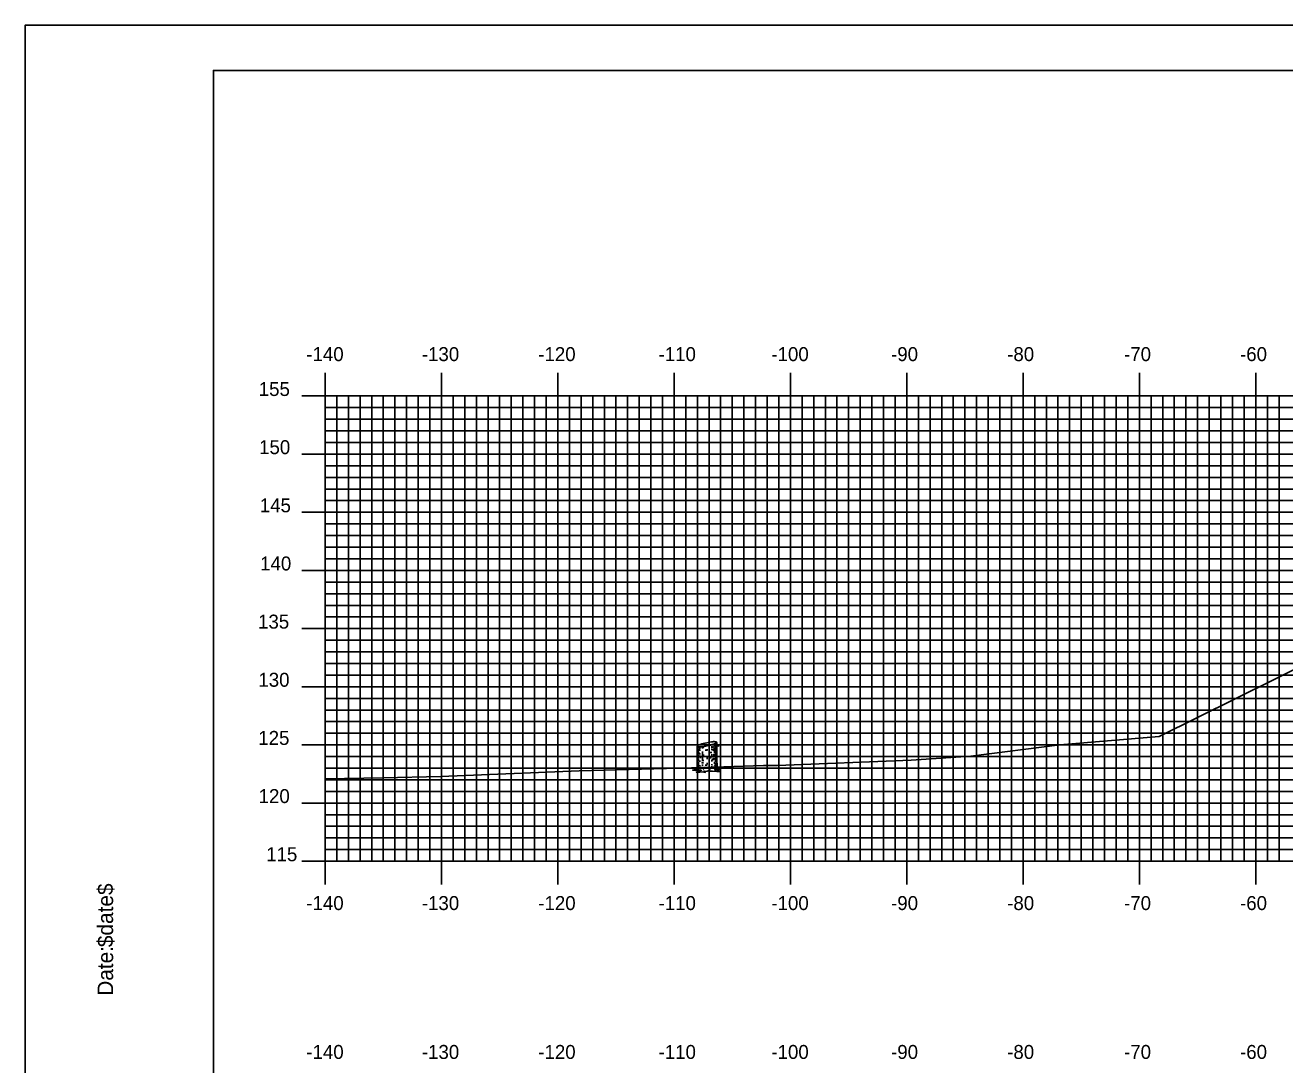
# Model space of a CAD drawing. Extents: x 851360 to 851703, y 364661 to 364881.
# Drawn here: x 851359.9 to 851468.2, y 364791.9 to 364881.3 of the extents above; entities that cross this region are included whole.
import ezdxf

# ---------------------------------------------------------------- set-up
doc = ezdxf.new("R2010")
doc.units = 0
for name, color, linetype in [('BORDER', 7, 'Continuous'), ('H_V ANNOTATION', 7, 'Continuous'), ('M_Trees_Conifer_Pay', 7, 'Continuous'), ('MAJOR', 7, 'Continuous'), ('MINOR', 7, 'Continuous'), ('PLOT BOUNDARY', 7, 'Continuous'), ('S_Roadway_Centerline', 7, 'Continuous')]:
    doc.layers.add(name, color=color, linetype=linetype)

msp = doc.modelspace()

# ---------------------------------------------------------------- linework, layer by layer
at = {"layer": 'BORDER'}
msp.add_lwpolyline([(851376.13, 364667.37), (851696.13, 364667.37), (851696.13, 364877.37), (851376.13, 364877.37)], close=True, dxfattribs=at)
at = {"layer": 'M_Trees_Conifer_Pay'}
for p, q in [((851417.72, 364817.53), (851417.72, 364819.26)), ((851417.77, 364819.22), (851417.77, 364818.75)), ((851417.83, 364819.21), (851417.83, 364819.11)), ((851417.83, 364819.03), (851417.83, 364818.83)), ((851417.95, 364819.2), (851417.95, 364818.97)), ((851418.17, 364819.22), (851418.17, 364819.05)), ((851418.58, 364818.99), (851418.58, 364818.89)), ((851418.97, 364819.26), (851418.97, 364819.06)), ((851418.97, 364819), (851418.97, 364818.92)), ((851419.2, 364819.46), (851419.2, 364819.23)), ((851419.2, 364819.15), (851419.2, 364819.1)), ((851419.25, 364818.96), (851419.2, 364818.9)), ((851419.32, 364819.52), (851419.32, 364819.36)), ((851419.32, 364819.29), (851419.32, 364819.16)), ((851419.32, 364818.97), (851419.32, 364818.64)), ((851419.39, 364817.94), (851419.39, 364819.59)), ((851417.77, 364818.68), (851417.77, 364818.37)), ((851417.77, 364818.33), (851417.77, 364817.83)), ((851417.83, 364818.77), (851417.83, 364818.57)), ((851417.83, 364818.53), (851417.83, 364818.19)), ((851417.83, 364818.14), (851417.83, 364818)), ((851417.83, 364817.9), (851417.83, 364817.52)), ((851417.95, 364818.93), (851417.95, 364818.85)), ((851417.95, 364818.45), (851417.95, 364818.31)), ((851417.95, 364818.04), (851417.95, 364817.9)), ((851418.17, 364818.81), (851418.17, 364818.58)), ((851418.17, 364818.33), (851418.17, 364818.18)), ((851418.17, 364818.14), (851418.17, 364817.96)), ((851418.58, 364818.37), (851418.58, 364818.3)), ((851418.58, 364818.27), (851418.58, 364818.13)), ((851418.97, 364818.57), (851418.97, 364818.46)), ((851418.97, 364818.1), (851418.97, 364817.95)), ((851419.2, 364818.76), (851419.2, 364818.63)), ((851419.2, 364818.52), (851419.2, 364818.41)), ((851419.2, 364818.27), (851419.2, 364818.13)), ((851419.2, 364817.91), (851419.2, 364817.73)), ((851419.32, 364818.6), (851419.32, 364818.44)), ((851419.32, 364818.39), (851419.32, 364818.17)), ((851419.32, 364818.14), (851419.32, 364818.07)), ((851419.32, 364818.03), (851419.32, 364817.86)), ((851417.77, 364817.78), (851417.77, 364817.53)), ((851417.95, 364817.63), (851417.95, 364817.54)), ((851417.95, 364817.14), (851418.12, 364817.2)), ((851418.17, 364817.69), (851418.17, 364817.53)), ((851418.39, 364817.08), (851418.26, 364817.14)), ((851418.58, 364817.83), (851418.58, 364817.68)), ((851418.97, 364817.72), (851418.97, 364817.63))]:
    msp.add_line(p, q, dxfattribs=at)
for points in [[(851419.17, 364819.05), (851419.14, 364818.97), (851419.14, 364818.9), (851419.17, 364818.84)], [(851419.2, 364819.09), (851419.24, 364819.01), (851419.29, 364819.07), (851419.35, 364819.14), (851419.44, 364819.33), (851419.5, 364819.38), (851419.53, 364819.39)], [(851419.22, 364818.84), (851419.25, 364818.96), (851419.32, 364819.08), (851419.35, 364819.15), (851419.42, 364819.29)], [(851419.43, 364819.32), (851419.51, 364819.33), (851419.58, 364819.23)], [(851419.39, 364817.94), (851419.44, 364817.68), (851419.45, 364817.41), (851419.51, 364817.28), (851419.65, 364817.25), (851419.42, 364817.21), (851419.42, 364817.21), (851419.42, 364817.17), (851419.67, 364817.07), (851419.4, 364817.09), (851419.04, 364817.11), (851418.72, 364817.1), (851418.73, 364817.18), (851418.58, 364817.1), (851418.39, 364817.08), (851418.41, 364817.01), (851418.15, 364817.05), (851417.93, 364817.02), (851417.63, 364817.04), (851417.92, 364817.1), (851417.95, 364817.14), (851417.79, 364817.2), (851417.55, 364817.21), (851417.31, 364817.21), (851417.65, 364817.27), (851417.7, 364817.35), (851417.72, 364817.53)], [(851417.9, 364818.56), (851417.9, 364818.66), (851417.94, 364818.63), (851417.94, 364818.54)], [(851419.04, 364818.16), (851419.05, 364818.09), (851419.1, 364818.1), (851419.09, 364818.26)], [(851417.77, 364817.49), (851417.75, 364817.41), (851417.73, 364817.31)], [(851417.85, 364817.47), (851417.85, 364817.35), (851417.8, 364817.26), (851417.79, 364817.2)], [(851418.01, 364817.49), (851418.01, 364817.36), (851417.92, 364817.26)], [(851418.24, 364817.25), (851418.31, 364817.35), (851418.33, 364817.49)], [(851418.73, 364817.18), (851418.8, 364817.32), (851418.81, 364817.42)], [(851418.98, 364817.55), (851418.99, 364817.42), (851419.06, 364817.38)], [(851419.25, 364817.16), (851419.24, 364817.3), (851419.17, 364817.43)], [(851419.21, 364817.66), (851419.29, 364817.55), (851419.29, 364817.38), (851419.42, 364817.21)], [(851419.31, 364817.8), (851419.32, 364817.66), (851419.37, 364817.59), (851419.38, 364817.39)]]:
    msp.add_lwpolyline(points, dxfattribs=at)
for centre, radius, start, end in [((851417.75, 364819.25), 0.0314, 156.5158, 169.2194), ((851417.75, 364819.25), 0.0264, 169.2194, 180.0315), ((851417.75, 364819.25), 0.0226, 180.0315, 191.7194), ((851417.75, 364819.25), 0.0226, 191.7194, 203.4074), ((851417.75, 364819.26), 0.0264, 203.4074, 214.2194), ((851417.75, 364819.08), 0.0334, 163.9485, 180), ((851417.75, 364819.08), 0.0334, 180, 196.0515), ((851417.76, 364819.08), 0.0441, 196.0515, 210), ((851417.8, 364819.23), 0.0817, 132.3887, 146.7194), ((851417.77, 364819.25), 0.0527, 146.7194, 156.5158), ((851417.75, 364819.26), 0.0314, 214.2194, 226.923), ((851417.77, 364819.27), 0.0527, 226.923, 236.7194), ((851417.78, 364819.09), 0.0624, 210, 228.7494), ((851417.91, 364819.1), 0.251, 124.2194, 132.3887), ((851417.78, 364819.3), 0.0817, 236.7194, 251.0501), ((851417.85, 364819.17), 0.172, 228.7494, 240), ((851417.84, 364819.46), 0.251, 251.0501, 259.2194), ((851418.22, 364818.65), 0.802, 108.0594, 124.2194), ((851418.05, 364819.52), 0.571, 240, 240.3367), ((851417.94, 364820), 0.802, 259.2194, 275.3794), ((851418.05, 364819.52), 0.571, 246.8597, 257.9846), ((851419.58, 364814.49), 5.18, 101.7194, 108.0594), ((851417.53, 364824.36), 5.18, 275.3794, 281.7194), ((851418.55, 364823.27), 4.12, 264.6955, 266.7331), ((851419.58, 364814.49), 5.18, 95.3794, 101.7194), ((851417.53, 364824.36), 5.18, 281.7194, 288.0594), ((851418.55, 364823.27), 4.12, 276.238, 278.1032), ((851419.17, 364818.85), 0.802, 79.2194, 95.3794), ((851418.89, 364820.2), 0.802, 288.0594, 304.2194), ((851419.06, 364819.75), 0.571, 278.1032, 284.3667), ((851419.06, 364819.9), 0.571, 284.4317, 292.4132), ((851419.06, 364819.75), 0.571, 297.0237, 300), ((851419.27, 364819.39), 0.251, 71.0501, 79.2194), ((851419.2, 364819.74), 0.251, 304.2194, 312.3887), ((851419.25, 364819.56), 0.172, 300, 311.2506), ((851419.25, 364819.4), 0.172, 300, 311.2506), ((851419.33, 364819.55), 0.0817, 56.7194, 71.0501), ((851419.34, 364819.57), 0.0527, 46.923, 56.7194), ((851419.31, 364819.62), 0.0817, 312.3887, 326.7194), ((851419.33, 364819.48), 0.0624, 311.2506, 330), ((851419.33, 364819.32), 0.0624, 311.2506, 330), ((851419.36, 364819.59), 0.0314, 34.2194, 46.923), ((851419.36, 364819.59), 0.0226, 11.7194, 23.4074), ((851419.36, 364819.59), 0.0264, 23.4074, 34.2194), ((851419.36, 364819.59), 0.0314, 336.5158, 349.2194), ((851419.34, 364819.6), 0.0527, 326.7194, 336.5158), ((851419.34, 364819.47), 0.0441, 330, 343.9485), ((851419.34, 364819.31), 0.0441, 330, 343.9485), ((851419.36, 364819.59), 0.0226, 0.0315, 11.7194), ((851419.36, 364819.59), 0.0264, 349.2194, 0.0315), ((851419.35, 364819.46), 0.0334, 343.9485, 354.2151), ((851419.35, 364819.31), 0.0334, 343.9485, 354.2151), ((851417.75, 364818.63), 0.0334, 163.9485, 180), ((851417.75, 364818.63), 0.0334, 180, 196.0515), ((851417.76, 364818.63), 0.0441, 196.0515, 210), ((851417.75, 364818.42), 0.0334, 163.9485, 180), ((851417.75, 364818.42), 0.0334, 180, 196.0515), ((851417.76, 364818.42), 0.0441, 196.0515, 210), ((851417.75, 364818.18), 0.0334, 163.9485, 180), ((851417.75, 364818.18), 0.0334, 180, 196.0515), ((851417.76, 364818.19), 0.0441, 196.0515, 210), ((851417.75, 364817.99), 0.0334, 163.9485, 180), ((851417.78, 364818.64), 0.0624, 210, 228.7494), ((851417.78, 364818.43), 0.0624, 210, 228.7494), ((851417.78, 364818.2), 0.0624, 210, 228.7494), ((851417.85, 364818.72), 0.172, 228.7494, 240), ((851417.85, 364818.51), 0.172, 228.7494, 240), ((851417.85, 364818.28), 0.172, 228.7494, 240), ((851418.05, 364819.31), 0.571, 240, 247.0587), ((851418.05, 364819.07), 0.571, 240, 240.3367), ((851418.05, 364818.86), 0.571, 240, 246.8597), ((851418.05, 364818.62), 0.571, 240, 246.8597), ((851418.04, 364818.43), 0.571, 241.2369, 248.0268), ((851418.05, 364818.86), 0.571, 259.2707, 261.8968), ((851418.55, 364822.38), 4.12, 261.8968, 263.1474), ((851418.55, 364822.59), 4.12, 264.081, 266.6676), ((851418.55, 364822.14), 4.12, 264.716, 266.3193), ((851418.55, 364823.03), 4.12, 268.0751, 270), ((851418.55, 364823.03), 4.12, 270, 270.3581), ((851418.55, 364822.38), 4.12, 270, 270.3581), ((851418.55, 364822.38), 4.12, 273.1493, 275.4569), ((851418.55, 364822.82), 4.12, 273.7052, 275.9504), ((851418.55, 364823.03), 4.12, 275.7849, 277.0558), ((851418.55, 364822.59), 4.12, 277.6125, 278.1032), ((851419.05, 364819.07), 0.571, 278.1032, 286.9296), ((851419.06, 364819.31), 0.571, 284.4493, 297.0429), ((851419.05, 364818.62), 0.571, 285.3983, 297.1896), ((851419.05, 364818.43), 0.571, 289.2907, 300), ((851419.05, 364819.07), 0.571, 297.1896, 300), ((851419.05, 364818.86), 0.571, 297.1896, 300), ((851419.25, 364818.72), 0.172, 300, 311.2506), ((851419.25, 364818.51), 0.172, 300, 311.2506), ((851419.25, 364818.08), 0.172, 300, 311.2506), ((851419.33, 364818.64), 0.0624, 311.2506, 330), ((851419.33, 364818.43), 0.0624, 311.2506, 330), ((851419.33, 364818), 0.0624, 311.2506, 330), ((851419.35, 364818.63), 0.0334, 343.9485, 354.2151), ((851419.34, 364818.63), 0.0441, 330, 343.9485), ((851419.35, 364818.42), 0.0334, 343.9485, 354.2151), ((851419.34, 364818.42), 0.0441, 330, 343.9485), ((851419.34, 364817.99), 0.0441, 330, 343.9485), ((851419.35, 364817.99), 0.0334, 343.9485, 354.2151), ((851419.35, 364818.87), 0.0334, 343.9485, 354.2151), ((851417.75, 364817.79), 0.0334, 163.9485, 180), ((851417.75, 364817.79), 0.0334, 180, 196.0515), ((851417.76, 364817.79), 0.0441, 196.0515, 210), ((851417.75, 364817.57), 0.0334, 163.9485, 180), ((851417.75, 364817.57), 0.0334, 180, 196.0515), ((851417.76, 364817.57), 0.0441, 196.0515, 210), ((851417.78, 364817.8), 0.0624, 210, 228.7494), ((851417.78, 364817.58), 0.0624, 210, 228.7494), ((851417.85, 364817.88), 0.172, 228.7494, 240), ((851417.85, 364817.66), 0.172, 228.7494, 240), ((851418.05, 364818.23), 0.571, 240, 246.8597), ((851418.05, 364818.01), 0.571, 240, 244.5314), ((851418.55, 364821.53), 4.12, 262.4438, 263.512), ((851418.55, 364821.94), 4.12, 263.4991, 265.8397), ((851418.55, 364821.75), 4.12, 267.8117, 270), ((851418.55, 364821.75), 4.12, 270, 270.1328), ((851418.55, 364821.75), 4.12, 275.7849, 276.7896), ((851418.55, 364821.53), 4.12, 277.3684, 278.1032), ((851419.05, 364818.01), 0.571, 278.1032, 281.637), ((851419.05, 364818.23), 0.571, 288.5067, 297.2721), ((851419.25, 364817.66), 0.172, 300, 311.2506), ((851419.33, 364817.58), 0.0624, 311.2506, 330), ((851419.35, 364817.57), 0.0334, 343.9485, 354.2151), ((851419.34, 364817.57), 0.0441, 330, 343.9485)]:
    msp.add_arc(centre, radius, start, end, dxfattribs=at)
at = {"layer": 'MAJOR'}
for p, q in [((851385.73, 364851.37), (851385.73, 364849.37)), ((851395.73, 364851.37), (851395.73, 364849.37)), ((851405.73, 364851.37), (851405.73, 364849.37)), ((851415.73, 364851.37), (851415.73, 364849.37)), ((851425.73, 364851.37), (851425.73, 364849.37)), ((851435.73, 364851.37), (851435.73, 364849.37)), ((851445.73, 364851.37), (851445.73, 364849.37)), ((851455.73, 364851.37), (851455.73, 364849.37)), ((851465.73, 364851.37), (851465.73, 364849.37)), ((851383.72, 364849.37), (851385.73, 364849.37)), ((851385.73, 364849.37), (851665.73, 364849.37)), ((851385.73, 364809.37), (851385.73, 364849.37)), ((851385.73, 364809.37), (851385.73, 364849.37)), ((851385.73, 364849.37), (851665.73, 364849.37)), ((851395.73, 364809.37), (851395.73, 364849.37)), ((851405.73, 364809.37), (851405.73, 364849.37)), ((851415.73, 364809.37), (851415.73, 364849.37)), ((851425.73, 364809.37), (851425.73, 364849.37)), ((851435.73, 364809.37), (851435.73, 364849.37)), ((851445.73, 364809.37), (851445.73, 364849.37)), ((851455.73, 364809.37), (851455.73, 364849.37)), ((851465.73, 364809.37), (851465.73, 364849.37)), ((851383.72, 364844.37), (851385.73, 364844.37)), ((851385.73, 364844.37), (851665.73, 364844.37)), ((851383.72, 364839.37), (851385.73, 364839.37)), ((851385.73, 364839.37), (851665.73, 364839.37)), ((851383.72, 364834.37), (851385.73, 364834.37)), ((851385.73, 364834.37), (851665.73, 364834.37)), ((851383.72, 364829.37), (851385.73, 364829.37)), ((851385.73, 364829.37), (851665.73, 364829.37)), ((851383.72, 364824.37), (851385.73, 364824.37)), ((851385.73, 364824.37), (851665.73, 364824.37)), ((851383.72, 364819.37), (851385.73, 364819.37)), ((851385.73, 364819.37), (851665.73, 364819.37)), ((851383.72, 364814.37), (851385.73, 364814.37)), ((851385.73, 364814.37), (851665.73, 364814.37)), ((851383.72, 364809.37), (851385.73, 364809.37)), ((851385.73, 364809.37), (851665.73, 364809.37)), ((851385.73, 364809.37), (851665.73, 364809.37)), ((851385.73, 364807.37), (851385.73, 364809.37)), ((851395.73, 364807.37), (851395.73, 364809.37)), ((851405.73, 364807.37), (851405.73, 364809.37)), ((851415.73, 364807.37), (851415.73, 364809.37)), ((851425.73, 364807.37), (851425.73, 364809.37)), ((851435.73, 364807.37), (851435.73, 364809.37)), ((851445.73, 364807.37), (851445.73, 364809.37)), ((851455.73, 364807.37), (851455.73, 364809.37)), ((851465.73, 364807.37), (851465.73, 364809.37))]:
    msp.add_line(p, q, dxfattribs=at)
at = {"layer": 'MINOR'}
for p, q in [((851386.73, 364809.37), (851386.73, 364849.37)), ((851387.73, 364809.37), (851387.73, 364849.37)), ((851388.73, 364809.37), (851388.73, 364849.37)), ((851389.73, 364809.37), (851389.73, 364849.37)), ((851390.73, 364809.37), (851390.73, 364849.37)), ((851391.73, 364809.37), (851391.73, 364849.37)), ((851392.73, 364809.37), (851392.73, 364849.37)), ((851393.73, 364809.37), (851393.73, 364849.37)), ((851394.73, 364809.37), (851394.73, 364849.37)), ((851396.73, 364809.37), (851396.73, 364849.37)), ((851397.73, 364809.37), (851397.73, 364849.37)), ((851398.73, 364809.37), (851398.73, 364849.37)), ((851399.73, 364809.37), (851399.73, 364849.37)), ((851400.73, 364809.37), (851400.73, 364849.37)), ((851401.73, 364809.37), (851401.73, 364849.37)), ((851402.73, 364809.37), (851402.73, 364849.37)), ((851403.73, 364809.37), (851403.73, 364849.37)), ((851404.73, 364809.37), (851404.73, 364849.37)), ((851406.73, 364809.37), (851406.73, 364849.37)), ((851407.73, 364809.37), (851407.73, 364849.37)), ((851408.73, 364809.37), (851408.73, 364849.37)), ((851409.73, 364809.37), (851409.73, 364849.37)), ((851410.73, 364809.37), (851410.73, 364849.37)), ((851411.73, 364809.37), (851411.73, 364849.37)), ((851412.73, 364809.37), (851412.73, 364849.37)), ((851413.73, 364809.37), (851413.73, 364849.37)), ((851414.73, 364809.37), (851414.73, 364849.37)), ((851416.73, 364809.37), (851416.73, 364849.37)), ((851417.73, 364809.37), (851417.73, 364849.37)), ((851418.73, 364809.37), (851418.73, 364849.37)), ((851419.73, 364809.37), (851419.73, 364849.37)), ((851420.73, 364809.37), (851420.73, 364849.37)), ((851421.73, 364809.37), (851421.73, 364849.37)), ((851422.73, 364809.37), (851422.73, 364849.37)), ((851423.73, 364809.37), (851423.73, 364849.37)), ((851424.73, 364809.37), (851424.73, 364849.37)), ((851426.73, 364809.37), (851426.73, 364849.37)), ((851427.73, 364809.37), (851427.73, 364849.37)), ((851428.73, 364809.37), (851428.73, 364849.37)), ((851429.73, 364809.37), (851429.73, 364849.37)), ((851430.73, 364809.37), (851430.73, 364849.37)), ((851431.73, 364809.37), (851431.73, 364849.37)), ((851432.73, 364809.37), (851432.73, 364849.37)), ((851433.73, 364809.37), (851433.73, 364849.37)), ((851434.73, 364809.37), (851434.73, 364849.37)), ((851436.73, 364809.37), (851436.73, 364849.37)), ((851437.73, 364809.37), (851437.73, 364849.37)), ((851438.73, 364809.37), (851438.73, 364849.37)), ((851439.73, 364809.37), (851439.73, 364849.37)), ((851440.73, 364809.37), (851440.73, 364849.37)), ((851441.73, 364809.37), (851441.73, 364849.37)), ((851442.73, 364809.37), (851442.73, 364849.37)), ((851443.73, 364809.37), (851443.73, 364849.37)), ((851444.73, 364809.37), (851444.73, 364849.37)), ((851446.73, 364809.37), (851446.73, 364849.37)), ((851447.73, 364809.37), (851447.73, 364849.37)), ((851448.73, 364809.37), (851448.73, 364849.37)), ((851449.73, 364809.37), (851449.73, 364849.37)), ((851450.73, 364809.37), (851450.73, 364849.37)), ((851451.73, 364809.37), (851451.73, 364849.37)), ((851452.73, 364809.37), (851452.73, 364849.37)), ((851453.73, 364809.37), (851453.73, 364849.37)), ((851454.73, 364809.37), (851454.73, 364849.37)), ((851456.73, 364809.37), (851456.73, 364849.37)), ((851457.73, 364809.37), (851457.73, 364849.37)), ((851458.73, 364809.37), (851458.73, 364849.37)), ((851459.73, 364809.37), (851459.73, 364849.37)), ((851460.73, 364809.37), (851460.73, 364849.37)), ((851461.73, 364809.37), (851461.73, 364849.37)), ((851462.73, 364809.37), (851462.73, 364849.37)), ((851463.73, 364809.37), (851463.73, 364849.37)), ((851464.73, 364809.37), (851464.73, 364849.37)), ((851466.73, 364809.37), (851466.73, 364849.37)), ((851467.73, 364809.37), (851467.73, 364849.37)), ((851385.73, 364848.37), (851665.73, 364848.37)), ((851385.73, 364848.37), (851387.73, 364848.37)), ((851385.73, 364847.37), (851665.73, 364847.37)), ((851385.73, 364847.37), (851387.73, 364847.37)), ((851385.73, 364846.37), (851665.73, 364846.37)), ((851385.73, 364846.37), (851387.73, 364846.37)), ((851385.73, 364845.37), (851665.73, 364845.37)), ((851385.73, 364845.37), (851387.73, 364845.37)), ((851385.73, 364843.37), (851665.73, 364843.37)), ((851385.73, 364843.37), (851387.73, 364843.37)), ((851385.73, 364842.37), (851665.73, 364842.37)), ((851385.73, 364842.37), (851387.73, 364842.37)), ((851385.73, 364841.37), (851665.73, 364841.37)), ((851385.73, 364841.37), (851387.73, 364841.37)), ((851385.73, 364840.37), (851665.73, 364840.37)), ((851385.73, 364840.37), (851387.73, 364840.37)), ((851385.73, 364838.37), (851665.73, 364838.37)), ((851385.73, 364838.37), (851387.73, 364838.37)), ((851385.73, 364837.37), (851665.73, 364837.37)), ((851385.73, 364837.37), (851387.73, 364837.37)), ((851385.73, 364836.37), (851665.73, 364836.37)), ((851385.73, 364836.37), (851387.73, 364836.37)), ((851385.73, 364835.37), (851665.73, 364835.37)), ((851385.73, 364835.37), (851387.73, 364835.37)), ((851385.73, 364833.37), (851665.73, 364833.37)), ((851385.73, 364833.37), (851387.73, 364833.37)), ((851385.73, 364832.37), (851665.73, 364832.37)), ((851385.73, 364832.37), (851387.73, 364832.37)), ((851385.73, 364831.37), (851665.73, 364831.37)), ((851385.73, 364831.37), (851387.73, 364831.37)), ((851385.73, 364830.37), (851665.73, 364830.37)), ((851385.73, 364830.37), (851387.73, 364830.37)), ((851385.73, 364828.37), (851665.73, 364828.37)), ((851385.73, 364828.37), (851387.73, 364828.37)), ((851385.73, 364827.37), (851665.73, 364827.37)), ((851385.73, 364827.37), (851387.73, 364827.37)), ((851385.73, 364826.37), (851665.73, 364826.37)), ((851385.73, 364826.37), (851387.73, 364826.37)), ((851385.73, 364825.37), (851665.73, 364825.37)), ((851385.73, 364825.37), (851387.73, 364825.37)), ((851385.73, 364823.37), (851665.73, 364823.37)), ((851385.73, 364823.37), (851387.73, 364823.37)), ((851385.73, 364822.37), (851665.73, 364822.37)), ((851385.73, 364822.37), (851387.73, 364822.37)), ((851385.73, 364821.37), (851665.73, 364821.37)), ((851385.73, 364821.37), (851387.73, 364821.37)), ((851385.73, 364820.37), (851665.73, 364820.37)), ((851385.73, 364820.37), (851387.73, 364820.37)), ((851385.73, 364818.37), (851665.73, 364818.37)), ((851385.73, 364818.37), (851387.73, 364818.37)), ((851385.73, 364817.37), (851665.73, 364817.37)), ((851385.73, 364817.37), (851387.73, 364817.37)), ((851385.73, 364816.37), (851665.73, 364816.37)), ((851385.73, 364816.37), (851387.73, 364816.37)), ((851385.73, 364815.37), (851665.73, 364815.37)), ((851385.73, 364815.37), (851387.73, 364815.37)), ((851385.73, 364813.37), (851665.73, 364813.37)), ((851385.73, 364813.37), (851387.73, 364813.37)), ((851385.73, 364812.37), (851665.73, 364812.37)), ((851385.73, 364812.37), (851387.73, 364812.37)), ((851385.73, 364811.37), (851665.73, 364811.37)), ((851385.73, 364811.37), (851387.73, 364811.37)), ((851385.73, 364810.37), (851665.73, 364810.37)), ((851385.73, 364810.37), (851387.73, 364810.37))]:
    msp.add_line(p, q, dxfattribs=at)
at = {"layer": 'PLOT BOUNDARY'}
msp.add_lwpolyline([(851359.94, 364661.25), (851699.94, 364661.25), (851699.94, 364881.25), (851359.94, 364881.25)], close=True, dxfattribs=at)
at = {"layer": 'S_Roadway_Centerline'}
msp.add_lwpolyline([(851385.73, 364816.45), (851390.71, 364816.55), (851395.66, 364816.66), (851407.58, 364817.13), (851418.27, 364817.43), (851423.41, 364817.59), (851424.63, 364817.61), (851436.12, 364818.05), (851441.25, 364818.39), (851448.89, 364819.39), (851457.43, 364820.1), (851470.62, 364826.62), (851476.78, 364829.62), (851484.99, 364834.07), (851487.64, 364835.46)], dxfattribs=at)

# ---------------------------------------------------------------- texts
at = {"layer": 'BORDER'}
for s, p in [('$date$', (851367.5, 364801.98)), ('Date:', (851367.5, 364797.8))]:
    msp.add_text(s, height=1.339, rotation=90, dxfattribs=at).set_placement(p)
at = {"layer": 'H_V ANNOTATION'}
for s, p in [('-140', (851384.11, 364852.37)), ('-130', (851394.04, 364852.37)), ('-120', (851404.05, 364852.37)), ('-110', (851414.39, 364852.37)), ('-100', (851424.09, 364852.37)), ('-90', (851434.38, 364852.37)), ('-80', (851444.36, 364852.37)), ('-70', (851454.41, 364852.37)), ('-60', (851464.38, 364852.37)), ('155', (851380.02, 364849.37)), ('150', (851380.05, 364844.37)), ('145', (851380.11, 364839.37)), ('140', (851380.14, 364834.37)), ('135', (851379.96, 364829.37)), ('130', (851379.99, 364824.37)), ('125', (851379.98, 364819.37)), ('120', (851380.01, 364814.37)), ('115', (851380.66, 364809.37)), ('-140', (851384.11, 364805.17)), ('-130', (851394.04, 364805.17)), ('-120', (851404.05, 364805.17)), ('-110', (851414.39, 364805.17)), ('-100', (851424.09, 364805.17)), ('-90', (851434.38, 364805.17)), ('-80', (851444.36, 364805.17)), ('-70', (851454.41, 364805.17)), ('-60', (851464.38, 364805.17)), ('-140', (851384.11, 364792.37)), ('-130', (851394.04, 364792.37)), ('-120', (851404.05, 364792.37)), ('-110', (851414.39, 364792.37)), ('-100', (851424.09, 364792.37)), ('-90', (851434.38, 364792.37)), ('-80', (851444.36, 364792.37)), ('-70', (851454.41, 364792.37)), ('-60', (851464.38, 364792.37))]:
    msp.add_text(s, height=1.2, dxfattribs=at).set_placement(p)
at = {"layer": 'MAJOR'}
msp.add_text('-', height=0.012, dxfattribs=at).set_placement((851385.72, 364809.37))

doc.saveas('drawing.dxf')
